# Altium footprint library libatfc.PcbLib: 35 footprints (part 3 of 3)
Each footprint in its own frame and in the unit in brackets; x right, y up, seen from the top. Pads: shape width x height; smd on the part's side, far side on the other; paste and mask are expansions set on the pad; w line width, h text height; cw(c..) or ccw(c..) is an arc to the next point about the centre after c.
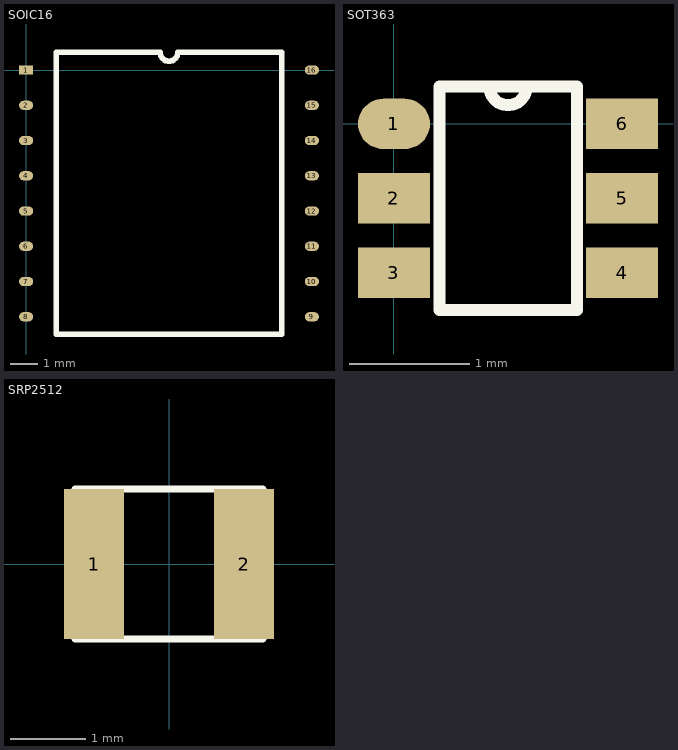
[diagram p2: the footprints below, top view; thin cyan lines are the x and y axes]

## SOIC16 [mm]
height 2.65
pads (16):
  rect 0.51x0.33 smd: 1(0,0)
  oval 0.51x0.33 smd: 2(0,-1.27) 3(0,-2.54) 4(0,-3.81) 5(0,-5.08) 6(0,-6.35) 7(0,-7.62) 8(0,-8.89) 9(10.3,-8.89) 10(10.3,-7.62) 11(10.3,-6.35) 12(10.3,-5.08) 13(10.3,-3.81) 14(10.3,-2.54) 15(10.3,-1.27) 16(10.3,0)
Top Overlay:
  lines w0.2: 1.09,-9.525 9.21,-9.525 9.21,0.635 5.467,0.635 cw(c5.15,0.635) 4.832,0.635 1.09,0.635 1.09,-9.525

## SOT363 [mm]
pads (6):
  oval 0.6x0.42 smd: 1(0,0)
  rect 0.6x0.42 smd: 2(0,-0.62) 3(0,-1.24) 4(1.9,-1.24) 5(1.9,-0.62) 6(1.9,0)
Top Overlay:
  lines w0.1: 0.381,-1.55 0.381,-1.109 0.381,-0.639 0.381,0.31 1.105,0.31 cw(c0.95,0.31) 0.795,0.31 1.524,0.31 1.524,-1.55 0.381,-1.55

## SRP2512 [mm]
height 1.2
pads (2):
  rect 0.8x2 smd: 1(-1,0) 2(1,0)
Top Overlay:
  lines w0.1: -1.25,-1 -1.25,1 1.25,1 1.25,-1 -1.25,-1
